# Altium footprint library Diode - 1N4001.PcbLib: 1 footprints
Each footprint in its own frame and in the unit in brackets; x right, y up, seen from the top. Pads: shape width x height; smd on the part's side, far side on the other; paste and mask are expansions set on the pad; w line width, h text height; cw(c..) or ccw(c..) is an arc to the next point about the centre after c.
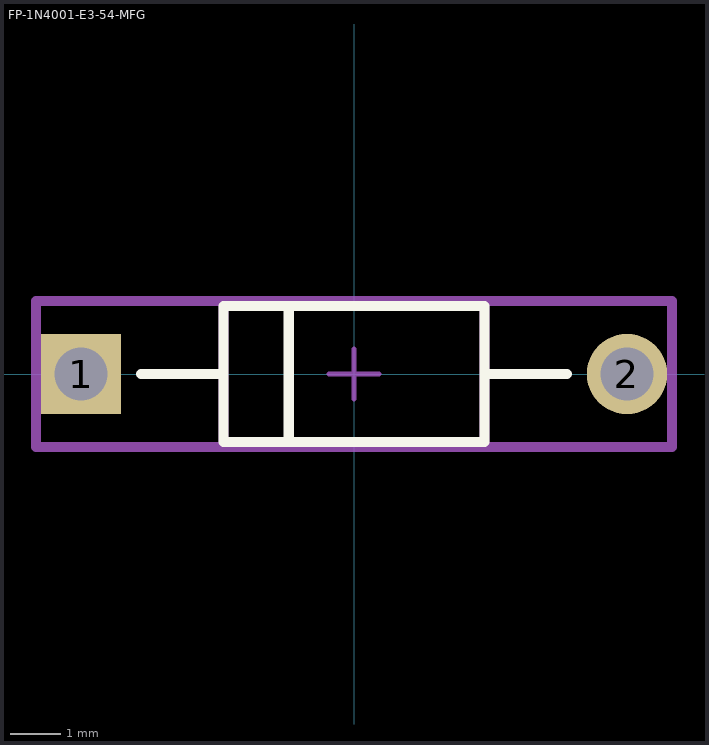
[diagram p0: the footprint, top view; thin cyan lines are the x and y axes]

## FP-1N4001-E3-54-MFG [mm]
pads (2):
  rect 1.6x1.6 hole 1.05 paste-2539.97 mask+0: 1(-5.438,0)
  round 1.6 hole 1.05 paste-2539.97 mask+0: 2(5.438,0)
Top Overlay:
  lines w0.2: -4.238,0 -2.6,0 ; -1.3,-1.28 -1.3,1.28 ; 2.6,0 4.238,0 ; -2.6,-1.35 -2.6,1.35 2.6,1.35 2.6,-1.35 -2.6,-1.35
Top Assembly:
  lines w0.2: -6.338,-1.45 -6.338,1.45 6.338,1.45 6.338,-1.45 -6.338,-1.45
  text ".Designator" at 0,0.188 h1
Top 3D Body:
  lines w0.2: -2.6,-1.35 -2.6,1.35 2.6,1.35 2.6,-1.35 -2.6,-1.35
Top Courtyard:
  lines w0.2: -6.338,-1.45 -6.338,1.45 6.338,1.45 6.338,-1.45 -6.338,-1.45
Top Component Center:
  lines w0.1: -0.5,0 0.5,0 ; 0,-0.5 0,0.5
3D body "Diode_Vishay_1N4001-E3-54_eec.STEP": height 0.25, standoff 0, extent -6.338,-1.45 6.338,1.45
